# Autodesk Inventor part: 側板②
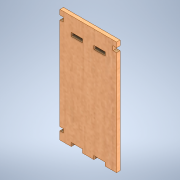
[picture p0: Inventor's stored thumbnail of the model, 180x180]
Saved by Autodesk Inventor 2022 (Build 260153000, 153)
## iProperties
Created: 2024-11
Part Number: 側板②
Material: MDF 中密度繊維ボード
Document SubType Name: Modeling
Designer: shimizu
Density: 0.8 g/cm^3
Appearance: サクラ材 - ナチュラル 抑えた光沢
Author: shimizu
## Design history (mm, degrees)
sketch "スケッチ1"
  geometry: L1 (-20.243, 58.107)-(19.757, 58.107); L2 (-4.243, -21.893)-(-4.243, -19.393); L3 (-4.243, -19.393)-(-12.243, -19.393); L4 (-12.243, -19.393)-(-12.243, -21.893); L5 (11.757, -21.893)-(11.757, -19.393); L6 (11.757, -19.393)-(3.757, -19.393); L7 (3.757, -19.393)-(3.757, -21.893); L8 (-12.243, 48.107)-(-4.243, 48.107); L9 (-4.243, 48.107)-(-4.243, 45.607); L10 (-4.243, 45.607)-(-12.243, 45.607); L11 (-12.243, 45.607)-(-12.243, 48.107); L12 (3.757, 48.107)-(11.757, 48.107); L13 (11.757, 48.107)-(11.757, 45.607); L14 (11.757, 45.607)-(3.757, 45.607); L15 (3.757, 45.607)-(3.757, 48.107); L16 (-12.243, -21.893)-(-20.243, -21.893); L17 (19.757, -21.893)-(11.757, -21.893); L18 (3.757, -21.893)-(-4.243, -21.893); L19 (-20.243, 54.607)-(-17.743, 54.607); L20 (-17.743, 54.607)-(-17.743, 51.607); L21 (-17.743, 51.607)-(-20.243, 51.607); L22 (19.757, 54.607)-(17.257, 54.607); L23 (17.257, 54.607)-(17.257, 51.607); L24 (17.257, 51.607)-(19.757, 51.607); L25 (-20.243, -21.893)-(-20.243, 51.607); L26 (-20.243, 54.607)-(-20.243, 58.107); L27 (19.757, 58.107)-(19.757, 54.607); L28 (19.757, 51.607)-(19.757, -21.893); L29 (19.757, 42.426)-(17.257, 42.426); L30 (17.257, 42.426)-(17.257, 39.926); L31 (17.257, 39.926)-(19.757, 39.926); L32 (19.757, 39.926)-(19.757, 42.426); L33 (-20.243, -13.703)-(-17.743, -13.703); L34 (-17.743, -13.703)-(-17.743, -16.213); L35 (-17.743, -16.213)-(-20.243, -16.213); L36 (-20.243, -16.213)-(-20.243, -13.703); 3 further points
  constraints: 72 end point, 19 parallel, 8 perpendicular, 7 horizontal, 2 point on line
  dimensions: "d27" = 80 distance between parallel lines of L17 L1; "d28" = 40 distance between parallel lines of L25 L28; "d29" = 3.181 distance between parallel lines of L29 L14; "d30" = 2.5 distance of L30.end L31.end; "d31" = 2.5 distance between parallel lines of L16 L3; "d32" = 3.18 distance between parallel lines of L3 L35; "d33" = 2.51 distance of L33.end L34.end; "d34" = 2.5 distance between parallel lines of L36 L34; "d35" = 2.5 distance between parallel lines of L31 L29
extrude "押し出し1" new body sketch "スケッチ1" distance "d13" = 2.5; taper "d14" = 0 deg
node "ソリッド1"
